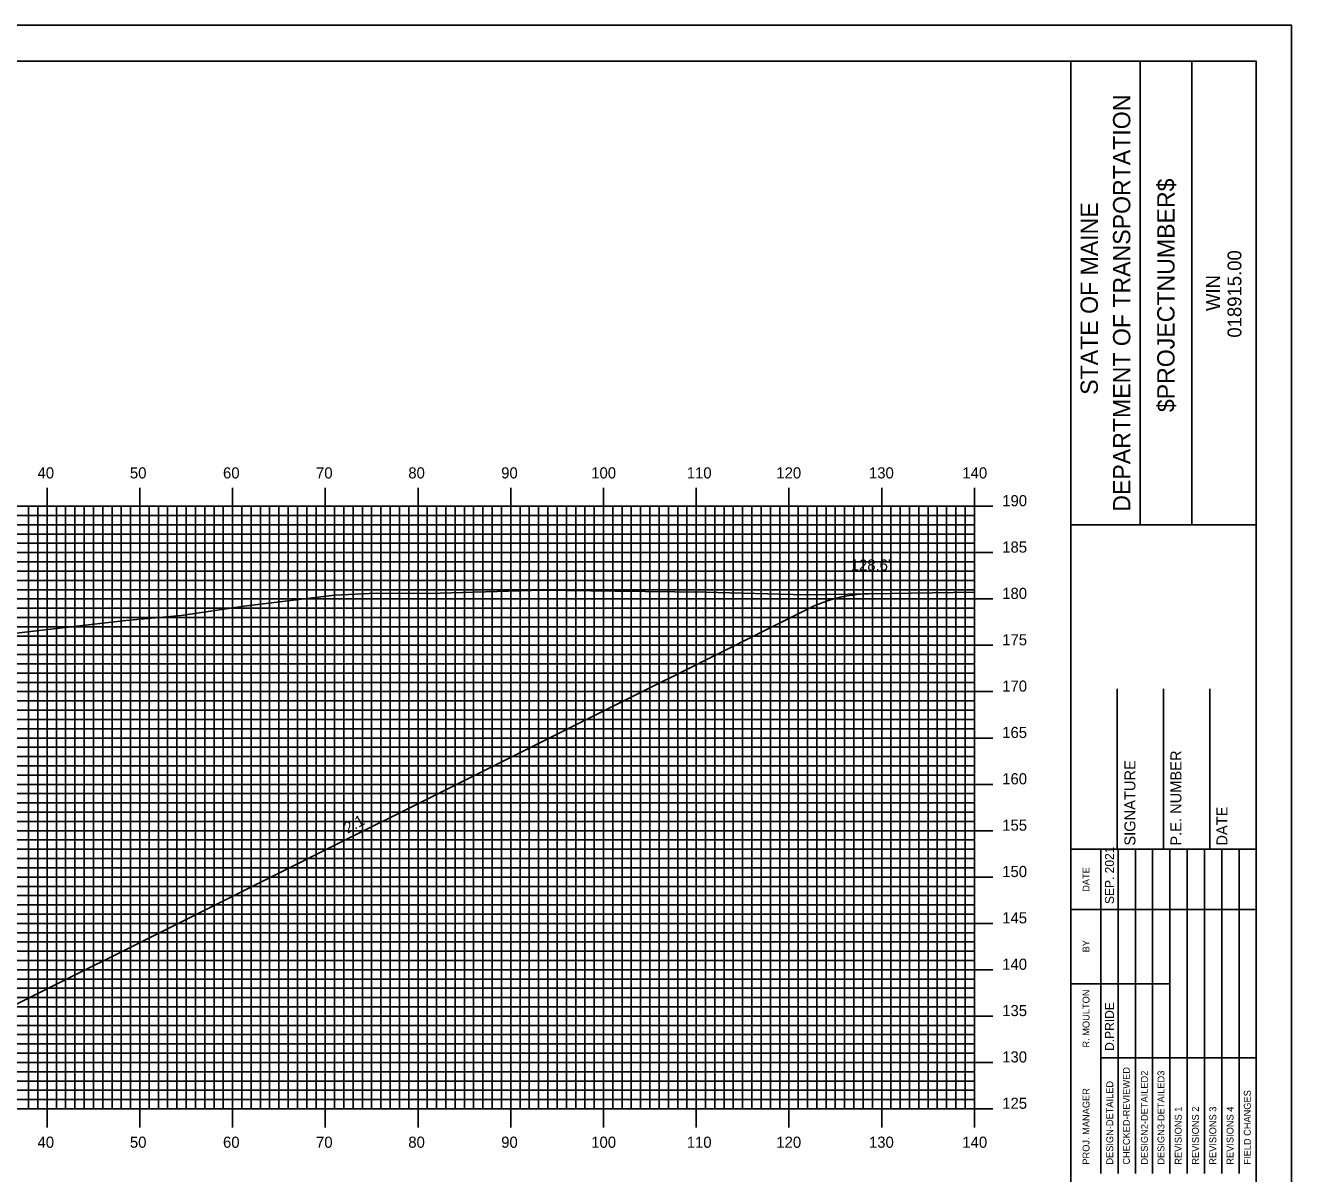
# Model space of a CAD drawing. Extents: x 1784221 to 1784564, y 442591 to 442811.
# Drawn here: x 1784424.7 to 1784561.2, y 442686.7 to 442810.5 of the extents above; entities that cross this region are included whole.
import ezdxf

# ---------------------------------------------------------------- set-up
doc = ezdxf.new("R2010")
doc.units = 0
for name, color, linetype in [('ANNOTATION', 7, 'Continuous'), ('BORDER', 7, 'Continuous'), ('D_Roadway_Centerline', 7, 'Continuous'), ('D_Roadway_SlopeLines', 7, 'Continuous'), ('D_Text_Standard', 7, 'Continuous'), ('H_V ANNOTATION', 7, 'Continuous'), ('MAJOR', 7, 'Continuous'), ('MINOR', 7, 'Continuous'), ('PLOT BOUNDARY', 7, 'Continuous'), ('S_Roadway_Centerline', 7, 'Continuous')]:
    doc.layers.add(name, color=color, linetype=linetype)

msp = doc.modelspace()

# ---------------------------------------------------------------- linework, layer by layer
at = {"layer": 'BORDER'}
for p, q in [((1784537.4, 442596.67), (1784537.4, 442806.67)), ((1784544.86, 442756.66), (1784544.86, 442806.66)), ((1784550.45, 442756.66), (1784550.45, 442806.66)), ((1784537.4, 442756.65), (1784557.4, 442756.65)), ((1784537.4, 442756.65), (1784557.4, 442756.65)), ((1784542.4, 442721.67), (1784542.4, 442738.97)), ((1784542.4, 442721.67), (1784542.4, 442738.97)), ((1784547.4, 442721.67), (1784547.4, 442738.97)), ((1784547.4, 442721.67), (1784547.4, 442738.97)), ((1784552.4, 442721.67), (1784552.4, 442738.97)), ((1784552.4, 442721.67), (1784552.4, 442738.97)), ((1784537.4, 442721.67), (1784557.4, 442721.67)), ((1784537.4, 442721.67), (1784557.4, 442721.67))]:
    msp.add_line(p, q, dxfattribs=at)
msp.add_lwpolyline([(1784237.4, 442596.67), (1784557.4, 442596.67), (1784557.4, 442806.67), (1784237.4, 442806.67)], close=True, dxfattribs=at)
for points in [[(1784540.63, 442715.17), (1784540.63, 442721.67)], [(1784540.63, 442715.17), (1784540.63, 442721.67)], [(1784542.49, 442686.68), (1784542.49, 442721.67)], [(1784542.49, 442686.68), (1784542.49, 442721.67)], [(1784544.36, 442721.67), (1784544.36, 442686.68)], [(1784544.36, 442721.67), (1784544.36, 442686.68)], [(1784546.22, 442686.68), (1784546.22, 442721.67)], [(1784546.22, 442686.68), (1784546.22, 442721.67)], [(1784548.08, 442686.68), (1784548.08, 442721.67)], [(1784548.08, 442686.68), (1784548.08, 442721.67)], [(1784549.95, 442686.68), (1784549.95, 442721.67)], [(1784549.95, 442686.68), (1784549.95, 442721.67)], [(1784551.81, 442686.68), (1784551.81, 442721.67)], [(1784551.81, 442686.68), (1784551.81, 442721.67)], [(1784553.67, 442686.68), (1784553.67, 442721.67)], [(1784553.67, 442686.68), (1784553.67, 442721.67)], [(1784555.54, 442686.68), (1784555.54, 442721.67)], [(1784555.54, 442686.68), (1784555.54, 442721.67)], [(1784540.63, 442686.68), (1784540.63, 442720.26)], [(1784540.63, 442686.68), (1784540.63, 442720.26)], [(1784537.4, 442715.17), (1784557.4, 442715.17)], [(1784537.4, 442715.17), (1784557.4, 442715.17)], [(1784537.4, 442707.17), (1784540.63, 442707.17)], [(1784537.4, 442707.17), (1784540.63, 442707.17)], [(1784540.63, 442707.17), (1784548.08, 442707.17)], [(1784540.63, 442707.17), (1784548.08, 442707.17)], [(1784540.63, 442699.17), (1784557.4, 442699.17)], [(1784540.63, 442699.17), (1784557.4, 442699.17)]]:
    msp.add_lwpolyline(points, dxfattribs=at)
at = {"layer": 'D_Roadway_Centerline'}
msp.add_lwpolyline([(1784294.99, 442727.41), (1784296.24, 442727.5), (1784297.49, 442727.38), (1784298.74, 442727.06), (1784299.99, 442726.54), (1784352.83, 442700.12), (1784356.83, 442701.12), (1784367, 442703.67), (1784375, 442703.99), (1784387, 442704.25), (1784399, 442704.52), (1784407, 442704.2), (1784417.11, 442701.67), (1784509.14, 442747.63)], dxfattribs=at)
at = {"layer": 'D_Roadway_SlopeLines'}
msp.add_line((1784509.14, 442747.63), (1784509.14, 442747.63), dxfattribs=at)
msp.add_arc((1784515.84, 442734.22), 15, 90.9811, 116.5651, dxfattribs=at)
at = {"layer": 'MAJOR'}
for p, q in [((1784427, 442760.67), (1784427, 442758.67)), ((1784437, 442760.67), (1784437, 442758.67)), ((1784447, 442760.67), (1784447, 442758.67)), ((1784457, 442760.67), (1784457, 442758.67)), ((1784467, 442760.67), (1784467, 442758.67)), ((1784477, 442760.67), (1784477, 442758.67)), ((1784487, 442760.67), (1784487, 442758.67)), ((1784497, 442760.67), (1784497, 442758.67)), ((1784507, 442760.67), (1784507, 442758.67)), ((1784517, 442760.67), (1784517, 442758.67)), ((1784527, 442760.67), (1784527, 442758.67)), ((1784247, 442758.67), (1784527, 442758.67)), ((1784247, 442758.67), (1784527, 442758.67)), ((1784427, 442693.67), (1784427, 442758.67)), ((1784437, 442693.67), (1784437, 442758.67)), ((1784447, 442693.67), (1784447, 442758.67)), ((1784457, 442693.67), (1784457, 442758.67)), ((1784467, 442693.67), (1784467, 442758.67)), ((1784477, 442693.67), (1784477, 442758.67)), ((1784487, 442693.67), (1784487, 442758.67)), ((1784497, 442693.67), (1784497, 442758.67)), ((1784507, 442693.67), (1784507, 442758.67)), ((1784517, 442693.67), (1784517, 442758.67)), ((1784529, 442758.67), (1784525, 442758.67)), ((1784527, 442693.67), (1784527, 442758.67)), ((1784527, 442693.67), (1784527, 442758.67)), ((1784247, 442753.67), (1784527, 442753.67)), ((1784529, 442753.67), (1784525, 442753.67)), ((1784247, 442748.67), (1784527, 442748.67)), ((1784529, 442748.67), (1784525, 442748.67)), ((1784247, 442743.67), (1784527, 442743.67)), ((1784529, 442743.67), (1784525, 442743.67)), ((1784247, 442738.67), (1784527, 442738.67)), ((1784529, 442738.67), (1784525, 442738.67)), ((1784247, 442733.67), (1784527, 442733.67)), ((1784529, 442733.67), (1784525, 442733.67)), ((1784247, 442728.67), (1784527, 442728.67)), ((1784529, 442728.67), (1784525, 442728.67)), ((1784247, 442723.67), (1784527, 442723.67)), ((1784529, 442723.67), (1784525, 442723.67)), ((1784247, 442718.67), (1784527, 442718.67)), ((1784529, 442718.67), (1784525, 442718.67)), ((1784247, 442713.67), (1784527, 442713.67)), ((1784529, 442713.67), (1784525, 442713.67)), ((1784247, 442708.67), (1784527, 442708.67)), ((1784529, 442708.67), (1784525, 442708.67)), ((1784247, 442703.67), (1784527, 442703.67)), ((1784529, 442703.67), (1784525, 442703.67)), ((1784247, 442698.67), (1784527, 442698.67)), ((1784529, 442698.67), (1784525, 442698.67)), ((1784247, 442693.67), (1784527, 442693.67)), ((1784247, 442693.67), (1784527, 442693.67)), ((1784427, 442691.66), (1784427, 442693.67)), ((1784437, 442691.66), (1784437, 442693.67)), ((1784447, 442691.66), (1784447, 442693.67)), ((1784457, 442691.66), (1784457, 442693.67)), ((1784467, 442691.66), (1784467, 442693.67)), ((1784477, 442691.66), (1784477, 442693.67)), ((1784487, 442691.66), (1784487, 442693.67)), ((1784497, 442691.66), (1784497, 442693.67)), ((1784507, 442691.66), (1784507, 442693.67)), ((1784517, 442691.66), (1784517, 442693.67)), ((1784529, 442693.67), (1784525, 442693.67)), ((1784527, 442691.66), (1784527, 442693.67))]:
    msp.add_line(p, q, dxfattribs=at)
at = {"layer": 'MINOR'}
for p, q in [((1784247, 442757.67), (1784527, 442757.67)), ((1784425, 442693.67), (1784425, 442758.67)), ((1784426, 442693.67), (1784426, 442758.67)), ((1784428, 442693.67), (1784428, 442758.67)), ((1784429, 442693.67), (1784429, 442758.67)), ((1784430, 442693.67), (1784430, 442758.67)), ((1784431, 442693.67), (1784431, 442758.67)), ((1784432, 442693.67), (1784432, 442758.67)), ((1784433, 442693.67), (1784433, 442758.67)), ((1784434, 442693.67), (1784434, 442758.67)), ((1784435, 442693.67), (1784435, 442758.67)), ((1784436, 442693.67), (1784436, 442758.67)), ((1784438, 442693.67), (1784438, 442758.67)), ((1784439, 442693.67), (1784439, 442758.67)), ((1784440, 442693.67), (1784440, 442758.67)), ((1784441, 442693.67), (1784441, 442758.67)), ((1784442, 442693.67), (1784442, 442758.67)), ((1784443, 442693.67), (1784443, 442758.67)), ((1784444, 442693.67), (1784444, 442758.67)), ((1784445, 442693.67), (1784445, 442758.67)), ((1784446, 442693.67), (1784446, 442758.67)), ((1784448, 442693.67), (1784448, 442758.67)), ((1784449, 442693.67), (1784449, 442758.67)), ((1784450, 442693.67), (1784450, 442758.67)), ((1784451, 442693.67), (1784451, 442758.67)), ((1784452, 442693.67), (1784452, 442758.67)), ((1784453, 442693.67), (1784453, 442758.67)), ((1784454, 442693.67), (1784454, 442758.67)), ((1784455, 442693.67), (1784455, 442758.67)), ((1784456, 442693.67), (1784456, 442758.67)), ((1784458, 442693.67), (1784458, 442758.67)), ((1784459, 442693.67), (1784459, 442758.67)), ((1784460, 442693.67), (1784460, 442758.67)), ((1784461, 442693.67), (1784461, 442758.67)), ((1784462, 442693.67), (1784462, 442758.67)), ((1784463, 442693.67), (1784463, 442758.67)), ((1784464, 442693.67), (1784464, 442758.67)), ((1784465, 442693.67), (1784465, 442758.67)), ((1784466, 442693.67), (1784466, 442758.67)), ((1784468, 442693.67), (1784468, 442758.67)), ((1784469, 442693.67), (1784469, 442758.67)), ((1784470, 442693.67), (1784470, 442758.67)), ((1784471, 442693.67), (1784471, 442758.67)), ((1784472, 442693.67), (1784472, 442758.67)), ((1784473, 442693.67), (1784473, 442758.67)), ((1784474, 442693.67), (1784474, 442758.67)), ((1784475, 442693.67), (1784475, 442758.67)), ((1784476, 442693.67), (1784476, 442758.67)), ((1784478, 442693.67), (1784478, 442758.67)), ((1784479, 442693.67), (1784479, 442758.67)), ((1784480, 442693.67), (1784480, 442758.67)), ((1784481, 442693.67), (1784481, 442758.67)), ((1784482, 442693.67), (1784482, 442758.67)), ((1784483, 442693.67), (1784483, 442758.67)), ((1784484, 442693.67), (1784484, 442758.67)), ((1784485, 442693.67), (1784485, 442758.67)), ((1784486, 442693.67), (1784486, 442758.67)), ((1784488, 442693.67), (1784488, 442758.67)), ((1784489, 442693.67), (1784489, 442758.67)), ((1784490, 442693.67), (1784490, 442758.67)), ((1784491, 442693.67), (1784491, 442758.67)), ((1784492, 442693.67), (1784492, 442758.67)), ((1784493, 442693.67), (1784493, 442758.67)), ((1784494, 442693.67), (1784494, 442758.67)), ((1784495, 442693.67), (1784495, 442758.67)), ((1784496, 442693.67), (1784496, 442758.67)), ((1784498, 442693.67), (1784498, 442758.67)), ((1784499, 442693.67), (1784499, 442758.67)), ((1784500, 442693.67), (1784500, 442758.67)), ((1784501, 442693.67), (1784501, 442758.67)), ((1784502, 442693.67), (1784502, 442758.67)), ((1784503, 442693.67), (1784503, 442758.67)), ((1784504, 442693.67), (1784504, 442758.67)), ((1784505, 442693.67), (1784505, 442758.67)), ((1784506, 442693.67), (1784506, 442758.67)), ((1784508, 442693.67), (1784508, 442758.67)), ((1784509, 442693.67), (1784509, 442758.67)), ((1784510, 442693.67), (1784510, 442758.67)), ((1784511, 442693.67), (1784511, 442758.67)), ((1784512, 442693.67), (1784512, 442758.67)), ((1784513, 442693.67), (1784513, 442758.67)), ((1784514, 442693.67), (1784514, 442758.67)), ((1784515, 442693.67), (1784515, 442758.67)), ((1784516, 442693.67), (1784516, 442758.67)), ((1784518, 442693.67), (1784518, 442758.67)), ((1784519, 442693.67), (1784519, 442758.67)), ((1784520, 442693.67), (1784520, 442758.67)), ((1784521, 442693.67), (1784521, 442758.67)), ((1784522, 442693.67), (1784522, 442758.67)), ((1784523, 442693.67), (1784523, 442758.67)), ((1784524, 442693.67), (1784524, 442758.67)), ((1784525, 442693.67), (1784525, 442758.67)), ((1784527, 442757.67), (1784525, 442757.67)), ((1784526, 442693.67), (1784526, 442758.67)), ((1784247, 442756.67), (1784527, 442756.67)), ((1784527, 442756.67), (1784525, 442756.67)), ((1784247, 442755.67), (1784527, 442755.67)), ((1784527, 442755.67), (1784525, 442755.67)), ((1784247, 442754.67), (1784527, 442754.67)), ((1784527, 442754.67), (1784525, 442754.67)), ((1784247, 442752.67), (1784527, 442752.67)), ((1784527, 442752.67), (1784525, 442752.67)), ((1784247, 442751.67), (1784527, 442751.67)), ((1784247, 442750.67), (1784527, 442750.67)), ((1784527, 442751.67), (1784525, 442751.67)), ((1784527, 442750.67), (1784525, 442750.67)), ((1784247, 442749.67), (1784527, 442749.67)), ((1784527, 442749.67), (1784525, 442749.67)), ((1784247, 442747.67), (1784527, 442747.67)), ((1784247, 442746.67), (1784527, 442746.67)), ((1784527, 442747.67), (1784525, 442747.67)), ((1784527, 442746.67), (1784525, 442746.67)), ((1784247, 442745.67), (1784527, 442745.67)), ((1784527, 442745.67), (1784525, 442745.67)), ((1784247, 442744.67), (1784527, 442744.67)), ((1784527, 442744.67), (1784525, 442744.67)), ((1784247, 442742.67), (1784527, 442742.67)), ((1784527, 442742.67), (1784525, 442742.67)), ((1784247, 442741.67), (1784527, 442741.67)), ((1784527, 442741.67), (1784525, 442741.67)), ((1784247, 442740.67), (1784527, 442740.67)), ((1784247, 442739.67), (1784527, 442739.67)), ((1784527, 442740.67), (1784525, 442740.67)), ((1784527, 442739.67), (1784525, 442739.67)), ((1784247, 442737.67), (1784527, 442737.67)), ((1784527, 442737.67), (1784525, 442737.67)), ((1784247, 442736.67), (1784527, 442736.67)), ((1784247, 442735.67), (1784527, 442735.67)), ((1784527, 442736.67), (1784525, 442736.67)), ((1784527, 442735.67), (1784525, 442735.67)), ((1784247, 442734.67), (1784527, 442734.67)), ((1784527, 442734.67), (1784525, 442734.67)), ((1784247, 442732.67), (1784527, 442732.67)), ((1784247, 442731.67), (1784527, 442731.67)), ((1784527, 442732.67), (1784525, 442732.67)), ((1784527, 442731.67), (1784525, 442731.67)), ((1784247, 442730.67), (1784527, 442730.67)), ((1784527, 442730.67), (1784525, 442730.67)), ((1784247, 442729.67), (1784527, 442729.67)), ((1784527, 442729.67), (1784525, 442729.67)), ((1784247, 442727.67), (1784527, 442727.67)), ((1784527, 442727.67), (1784525, 442727.67)), ((1784247, 442726.67), (1784527, 442726.67)), ((1784527, 442726.67), (1784525, 442726.67)), ((1784247, 442725.67), (1784527, 442725.67)), ((1784247, 442724.67), (1784527, 442724.67)), ((1784527, 442725.67), (1784525, 442725.67)), ((1784527, 442724.67), (1784525, 442724.67)), ((1784247, 442722.67), (1784527, 442722.67)), ((1784527, 442722.67), (1784525, 442722.67)), ((1784247, 442721.67), (1784527, 442721.67)), ((1784247, 442720.67), (1784527, 442720.67)), ((1784527, 442721.67), (1784525, 442721.67)), ((1784527, 442720.67), (1784525, 442720.67)), ((1784247, 442719.67), (1784527, 442719.67)), ((1784527, 442719.67), (1784525, 442719.67)), ((1784247, 442717.67), (1784527, 442717.67)), ((1784247, 442716.67), (1784527, 442716.67)), ((1784527, 442717.67), (1784525, 442717.67)), ((1784527, 442716.67), (1784525, 442716.67)), ((1784247, 442715.67), (1784527, 442715.67)), ((1784527, 442715.67), (1784525, 442715.67)), ((1784247, 442714.67), (1784527, 442714.67)), ((1784527, 442714.67), (1784525, 442714.67)), ((1784247, 442712.67), (1784527, 442712.67)), ((1784527, 442712.67), (1784525, 442712.67)), ((1784247, 442711.67), (1784527, 442711.67)), ((1784527, 442711.67), (1784525, 442711.67)), ((1784247, 442710.67), (1784527, 442710.67)), ((1784247, 442709.67), (1784527, 442709.67)), ((1784527, 442710.67), (1784525, 442710.67)), ((1784527, 442709.67), (1784525, 442709.67)), ((1784247, 442707.67), (1784527, 442707.67)), ((1784527, 442707.67), (1784525, 442707.67)), ((1784247, 442706.67), (1784527, 442706.67)), ((1784247, 442705.67), (1784527, 442705.67)), ((1784527, 442706.67), (1784525, 442706.67)), ((1784527, 442705.67), (1784525, 442705.67)), ((1784247, 442704.67), (1784527, 442704.67)), ((1784527, 442704.67), (1784525, 442704.67)), ((1784247, 442702.67), (1784527, 442702.67)), ((1784247, 442701.67), (1784527, 442701.67)), ((1784527, 442702.67), (1784525, 442702.67)), ((1784527, 442701.67), (1784525, 442701.67)), ((1784247, 442700.67), (1784527, 442700.67)), ((1784527, 442700.67), (1784525, 442700.67)), ((1784247, 442699.67), (1784527, 442699.67)), ((1784527, 442699.67), (1784525, 442699.67)), ((1784247, 442697.67), (1784527, 442697.67)), ((1784527, 442697.67), (1784525, 442697.67)), ((1784247, 442696.67), (1784527, 442696.67)), ((1784527, 442696.67), (1784525, 442696.67)), ((1784247, 442695.67), (1784527, 442695.67)), ((1784247, 442694.67), (1784527, 442694.67)), ((1784527, 442695.67), (1784525, 442695.67)), ((1784527, 442694.67), (1784525, 442694.67))]:
    msp.add_line(p, q, dxfattribs=at)
at = {"layer": 'PLOT BOUNDARY'}
msp.add_lwpolyline([(1784221.21, 442590.55), (1784561.21, 442590.55), (1784561.21, 442810.55), (1784221.21, 442810.55)], close=True, dxfattribs=at)
at = {"layer": 'S_Roadway_Centerline'}
msp.add_lwpolyline([(1784423.05, 442744.92), (1784435.49, 442746.33), (1784441.47, 442746.9), (1784448.26, 442747.88), (1784457.98, 442749.09), (1784462.48, 442749.3), (1784468.18, 442749.26), (1784480.42, 442749.63), (1784488.27, 442749.52), (1784497.92, 442749.4), (1784508.82, 442749.1), (1784527, 442749.41)], dxfattribs=at)

# ---------------------------------------------------------------- texts
at = {"layer": 'ANNOTATION'}
msp.add_text('2:1', height=1.2, rotation=28.6223, dxfattribs=at).set_placement((1784459.4, 442723.34))
at = {"layer": 'BORDER'}
for s, height, p in [('DEPARTMENT OF TRANSPORTATION', 1.8635, (1784543.81, 442758.08)), ('$PROJECTNUMBER$', 1.8635, (1784548.58, 442768.82)), ('STATE OF MAINE', 1.8635, (1784540.31, 442770.69)), ('018915.00', 1.491, (1784555.79, 442776.86)), ('WIN', 1.491, (1784553.47, 442779.73)), ('P.E. NUMBER', 1.1811, (1784549.32, 442722.06)), ('P.E. NUMBER', 1.1811, (1784549.32, 442722.06)), ('SIGNATURE', 1.181, (1784544.36, 442722.06)), ('SIGNATURE', 1.181, (1784544.36, 442722.06)), ('DATE', 1.181, (1784554.28, 442722.06)), ('DATE', 1.181, (1784554.28, 442722.06)), ('SEP. 2021', 0.969, (1784542.05, 442715.76)), ('DATE', 0.743, (1784539.41, 442717.08)), ('DATE', 0.743, (1784539.41, 442717.08)), ('BY', 0.743, (1784539.41, 442710.54)), ('BY', 0.743, (1784539.41, 442710.54)), ('R. MOULTON', 0.745, (1784539.41, 442700.28)), ('D.PRIDE', 0.969, (1784542.05, 442699.92)), ('CHECKED-REVIEWED', 0.7455, (1784543.76, 442687.65)), ('CHECKED-REVIEWED', 0.7455, (1784543.76, 442687.65)), ('DESIGN2-DETAILED2', 0.7455, (1784545.7, 442687.65)), ('DESIGN2-DETAILED2', 0.7455, (1784545.7, 442687.65)), ('DESIGN3-DETAILED3', 0.7455, (1784547.49, 442687.65)), ('DESIGN3-DETAILED3', 0.7455, (1784547.49, 442687.65)), ('DESIGN-DETAILED', 0.7455, (1784541.97, 442687.65)), ('DESIGN-DETAILED', 0.7455, (1784541.97, 442687.65)), ('PROJ. MANAGER', 0.7455, (1784539.41, 442687.65)), ('PROJ. MANAGER', 0.7455, (1784539.41, 442687.65)), ('FIELD CHANGES', 0.7455, (1784556.8, 442687.65)), ('FIELD CHANGES', 0.7455, (1784556.8, 442687.65)), ('REVISIONS 1', 0.7455, (1784549.35, 442687.65)), ('REVISIONS 1', 0.7455, (1784549.35, 442687.65)), ('REVISIONS 2', 0.7455, (1784551.21, 442687.65)), ('REVISIONS 2', 0.7455, (1784551.21, 442687.65)), ('REVISIONS 3', 0.7455, (1784553.08, 442687.65)), ('REVISIONS 3', 0.7455, (1784553.08, 442687.65)), ('REVISIONS 4', 0.7455, (1784554.94, 442687.65)), ('REVISIONS 4', 0.7455, (1784554.94, 442687.65))]:
    msp.add_text(s, height=height, rotation=90, dxfattribs=at).set_placement(p)
at = {"layer": 'D_Text_Standard'}
msp.add_text("128.6'", height=1.2, dxfattribs=at).set_placement((1784513.66, 442751.73))
at = {"layer": 'H_V ANNOTATION'}
for s, p in [('40', (1784425.97, 442761.67)), ('50', (1784435.93, 442761.67)), ('60', (1784445.97, 442761.67)), ('70', (1784456, 442761.67)), ('80', (1784465.95, 442761.67)), ('90', (1784475.97, 442761.67)), ('100', (1784485.68, 442761.67)), ('110', (1784495.98, 442761.67)), ('120', (1784505.64, 442761.67)), ('130', (1784515.63, 442761.67)), ('140', (1784525.7, 442761.67)), ('190', (1784530, 442758.67)), ('185', (1784530, 442753.67)), ('180', (1784530, 442748.67)), ('175', (1784530, 442743.67)), ('170', (1784530, 442738.67)), ('165', (1784530, 442733.67)), ('160', (1784530, 442728.67)), ('155', (1784530, 442723.67)), ('150', (1784530, 442718.67)), ('145', (1784530, 442713.67)), ('140', (1784530, 442708.67)), ('135', (1784530, 442703.67)), ('130', (1784530, 442698.67)), ('125', (1784530, 442693.67)), ('40', (1784425.97, 442689.47)), ('50', (1784435.93, 442689.47)), ('60', (1784445.97, 442689.47)), ('70', (1784456, 442689.47)), ('80', (1784465.95, 442689.47)), ('90', (1784475.97, 442689.47)), ('100', (1784485.68, 442689.47)), ('110', (1784495.98, 442689.47)), ('120', (1784505.64, 442689.47)), ('130', (1784515.63, 442689.47)), ('140', (1784525.7, 442689.47))]:
    msp.add_text(s, height=1.2, dxfattribs=at).set_placement(p)

doc.saveas('drawing.dxf')
